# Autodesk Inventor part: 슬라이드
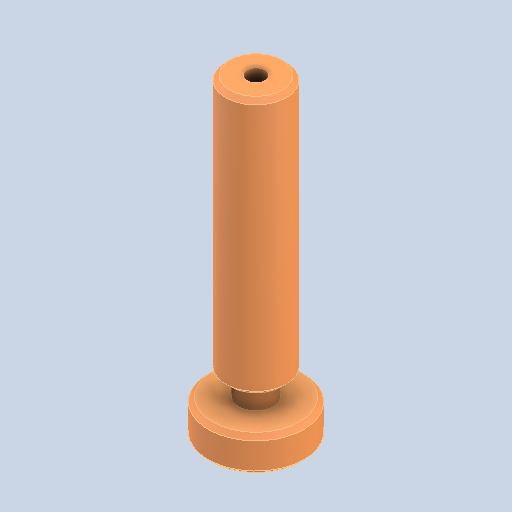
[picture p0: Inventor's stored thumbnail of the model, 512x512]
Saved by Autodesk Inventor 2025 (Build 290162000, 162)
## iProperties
Created: 2024-07
Part Number: 슬라이드
Material: 강철, 연강
Document SubType Name: Modeling
Designer: deana
Density: 7.86 g/cm^3
Appearance: 기본값
Author: jhkim
Sending System: Autodesk Inventor 2025
Preprocessor: ST-DEVELOPER v20
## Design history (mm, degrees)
feature "솔리드1"
node "솔리드2"
